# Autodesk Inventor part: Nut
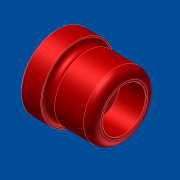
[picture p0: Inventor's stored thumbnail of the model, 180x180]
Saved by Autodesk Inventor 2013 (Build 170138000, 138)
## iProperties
Shininess: 20.0
Length Units: 11269
Angle Units: 11279
Time Units: 11290
Mass Units: 11283
Length Display Precision: 3
Angle Display Precision: 2
Created: 2001-04
Part Number: Nut
Material: Standard
Document SubType Name: Modellieren
Designer: dl
Density: 1 g/cm^3
Density: 0.0
Volumn: 0.0
Area: 0.0
PropertySet Name: Model Information
Control State: 0
Master: False
Checked Out: False
Author: dl
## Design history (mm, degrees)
body "Solid1"
revolve "Revolution1" stored, may be unused: angle "d9" = 90 deg
fillet "Fillet1" dims "d10" = 2
sketch "Sketch2"
  geometry: C1 r 5.5 at (0, 0) reference; 1 further point
  constraints: 1 coincident
hole "Hole1" sketch "Sketch2" diameter "d11" = 10; stored, may be unused: countersink angle "d15" = 60 deg, drill point angle "d17" = 0 deg; dims "d12" = 6, "d13" = 4, "d14" = 2, "d16" = 6
fillet "Fillet2" dims "d18" = 0.1
sketch "Sketch3"
  geometry: C1 r 5.75 at (0, 0) reference; 1 further point
  constraints: 1 coincident
hole "Hole2" sketch "Sketch3" diameter "d19" = 4.134; stored, may be unused: countersink angle "d23" = 60 deg, drill point angle "d25" = 0 deg; dims "d20" = 6, "d21" = 4, "d22" = 2, "d24" = 6
chamfer "Chamfer1" distance "d26" = 0.4; stored, may be unused: second distance "d27" = 0.4, angle "d43" = 45 deg
chamfer "Chamfer2" distance "d28" = 0.5; stored, may be unused: second distance "d29" = 0.5, angle "d44" = 45 deg
workaxis "Work Axis1"
workplane "Work Plane1"
sketch "Sketch4"
  geometry: L1 (2.15, 0)-(2.5, 0.35); L2 (2.5, 0.35)-(2.5, -0.35); L3 (2.5, -0.35)-(2.15, 0); L4 (0.963, 2.067)-(0.963, -2.067) reference; L5 (2.5, 8)-(2.5, -8) reference; L6 (0.963, 0)-(6.496, 0)
  constraints: 8 end point, 1 midpoint, 1 perpendicular, 1 vertical
  dimensions: "d33" = 90 deg angle of L3 L1; "d34" = 45 deg angle of L2 L1; "d35" = 0.7 distance of L1.end L2.end; "d36" = 0 distance from line of L5 L1.end; "d37" = 0 distance from line of L6 L1.start
extrude "Extrusion1" cut sketch "Sketch4" distance "d38" = 10; taper "d39" = 0 deg
pattern_circular "Circular Pattern1" dims angle "d42" = 360 deg
sketch "Sketch1"
  geometry: L1 (0, -1.048)-(0, 1.702); L2 (0, 1.702)-(5, 1.702); L3 (5, 1.702)-(5, 1.452); L4 (16, 0.702)-(16, -6.798); L5 (16, -6.798)-(1.137, -6.798); L6 (0, -1.048)-(1.137, -1.048); L7 (1.137, -1.048)-(1.137, -6.798); L8 (7.25, 0.702)-(16, 0.702); A1 r 1.25 centre (6.25, 1.452) between (5, 1.452) and (7.25, 0.702)
  constraints: 16 end point, 5 parallel, 2 perpendicular, 2 point on circle, 1 centre point, 1 tangent, 1 vertical
  dimensions: "d1" = 7.5 distance of L4.start L4.end; "d3" = 8.5 distance from line of L5 L1.end; "d4" = 5.75 distance of L6.end L5.end; "d5" = 1.25 radius of A1; "d6" = 0.75 distance from line of L8 A1.centre; "d7" = 16 distance between parallel lines of L4 L1; "d8" = 5 distance of L1.end L2.end
other parameters: "d30" = 0, "d31" = 0
